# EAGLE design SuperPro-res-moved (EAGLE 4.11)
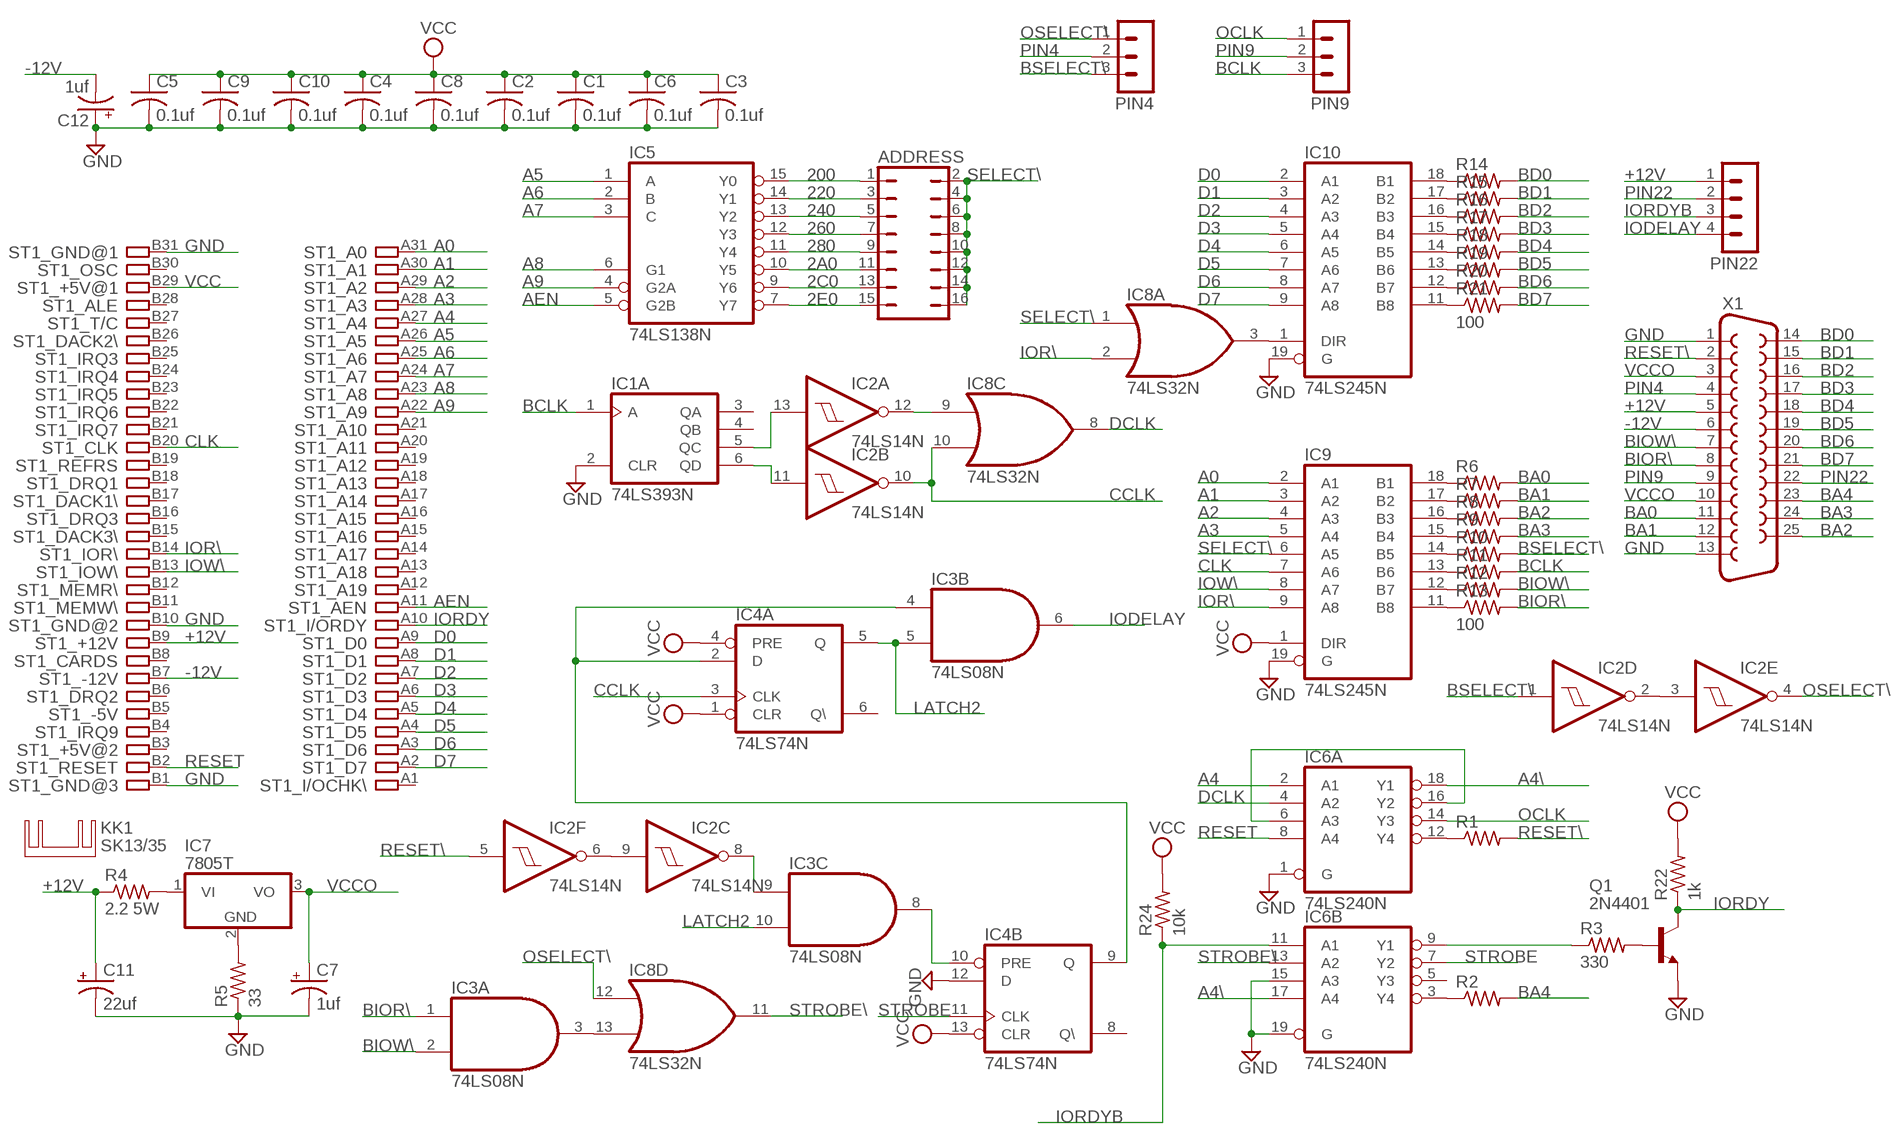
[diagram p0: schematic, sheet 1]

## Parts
ADDRESS  JP8Q  [JP8Q]
C1  0.1uf  C-US050-025X075  [C050-025X075]
C2  0.1uf  C-US050-025X075  [C050-025X075]
C3  0.1uf  C-US050-025X075  [C050-025X075]
C4  0.1uf  C-US050-025X075  [C050-025X075]
C5  0.1uf  C-US050-025X075  [C050-025X075]
C6  0.1uf  C-US050-025X075  [C050-025X075]
C7  1uf  CPOL-USE5-10.5  [E5-10,5]
C8  0.1uf  C-US050-025X075  [C050-025X075]
C9  0.1uf  C-US050-025X075  [C050-025X075]
C10  0.1uf  C-US050-025X075  [C050-025X075]
C11  22uf  CPOL-USE5-10.5  [E5-10,5]
C12  1uf  CPOL-USE5-10.5  [E5-10,5]
IC1  74LS393N  [DIL14]
IC2  74LS14N  [DIL14]
IC3  74LS08N  [DIL14]
IC4  74LS74N  [DIL14]
IC5  74LS138N  [DIL16]
IC6  74LS240N  [DIL20]
IC7  7805T  [TO220H]
IC8  74LS32N  [DIL14]
IC9  74LS245N  [DIL20]
IC10  74LS245N  [DIL20]
KK1  SK13/35  [SK13/35]
PIN4  MA03-1  [MA03-1]
PIN9  MA03-1  [MA03-1]
PIN22  MA04-1  [MA04-1]
Q1  2N4401  2N4416  [TO92]
R1  R-US_0207/10  [0207/10]
R2  R-US_0207/10  [0207/10]
R3  330  R-US_0207/10  [0207/10]
R4  2.2 5W  R-US_0922/22  [0922/22]
R5  33  R-US_0207/10  [0207/10]
R6  R-US_0207/10  [0207/10]
R7  R-US_0207/10  [0207/10]
R8  R-US_0207/10  [0207/10]
R9  R-US_0207/10  [0207/10]
R10  R-US_0207/10  [0207/10]
R11  R-US_0207/10  [0207/10]
R12  R-US_0207/10  [0207/10]
R13  100  R-US_0207/10  [0207/10]
R14  R-US_0207/10  [0207/10]
R15  R-US_0207/10  [0207/10]
R16  R-US_0207/10  [0207/10]
R17  R-US_0207/10  [0207/10]
R18  R-US_0207/10  [0207/10]
R19  R-US_0207/10  [0207/10]
R20  R-US_0207/10  [0207/10]
R21  100  R-US_0207/10  [0207/10]
R22  1k  R-US_0207/10  [0207/10]
R24  10k  R-US_0207/10  [0207/10]
ST1  IBM8BIT  [IBM8BIT]
X1  F25H  [F25H]

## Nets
2A0: ADDRESS.11 IC5.10(Y5)
2C0: ADDRESS.13 IC5.9(Y6)
2E0: ADDRESS.15 IC5.7(Y7)
200: ADDRESS.1 IC5.15(Y0)
220: ADDRESS.3 IC5.14(Y1)
240: ADDRESS.5 IC5.13(Y2)
260: ADDRESS.7 IC5.12(Y3)
280: ADDRESS.9 IC5.11(Y4)
+12V [Power]: C11.+ PIN22.1 R4.1 ST1.B9 X1.5
-12V [Power]: C12.- ST1.B7 X1.6
A0: IC9.2(A1) ST1.A31
A1: IC9.3(A2) ST1.A30
A2: IC9.4(A3) ST1.A29
A3: IC9.5(A4) ST1.A28
A4: IC6.2(A:A1) ST1.A27
A4\: IC6.17(B:A4) IC6.18(A:Y1)
A5: IC5.1(A) ST1.A26
A6: IC5.2(B) ST1.A25
A7: IC5.3(C) ST1.A24
A8: IC5.6(G1) ST1.A23
A9: IC5.4(G2A) ST1.A22
AEN: IC5.5(G2B) ST1.A11
BA0: R6.2 X1.11
BA1: R7.2 X1.12
BA2: R8.2 X1.25
BA3: R9.2 X1.24
BA4: R2.2 X1.23
BCLK: IC1.1(A:A) PIN9.3 R11.2
BD0: R14.2 X1.14
BD1: R15.2 X1.15
BD2: R16.2 X1.16
BD3: R17.2 X1.17
BD4: R18.2 X1.18
BD5: R19.2 X1.19
BD6: R20.2 X1.20
BD7: R21.2 X1.21
BIOR\: IC3.1(A:I0) R13.2 X1.8
BIOW\: IC3.2(A:I1) R12.2 X1.7
BSELECT\: IC2.1(D:I) PIN4.3 R10.2
CCLK: IC2.10(B:O) IC4.3(A:CLK) IC8.10(C:I1)
CLK: IC9.7(A6) ST1.B20
D0: IC10.2(A1) ST1.A9
D1: IC10.3(A2) ST1.A8
D2: IC10.4(A3) ST1.A7
D3: IC10.5(A4) ST1.A6
D4: IC10.6(A5) ST1.A5
D5: IC10.7(A6) ST1.A4
D6: IC10.8(A7) ST1.A3
D7: IC10.9(A8) ST1.A2
DCLK: IC6.4(A:A2) IC8.8(C:O)
GND: C1.2 C2.2 C3.2 C4.2 C5.2 C6.2 C7.- C8.2 C9.2 C10.2 C11.- C12.+ IC1.2(A:CLR) IC4.12(B:D) IC6.1(A:G) IC6.15(B:A3) IC6.19(B:G) IC9.19(G) IC10.19(G) Q1.3(E) R5.1 ST1.B1 ST1.B10 ST1.B31 X1.1 X1.13
IODELAY: IC3.6(B:O) PIN22.4
IOR\: IC8.2(A:I1) IC9.9(A8) ST1.B14
IORDY: Q1.1(C) R22.1 ST1.A10
IORDYB: IC6.11(B:A1) PIN22.3 R24.1
IOW\: IC9.8(A7) ST1.B13
LATCH2: IC3.5(B:I1) IC3.10(C:I1) IC4.5(A:Q)
N$1: IC8.3(A:O) IC10.1(DIR)
N$2 [Power]: IC7.2(GND) R5.2
N$3: IC10.13(B6) R19.1
N$4: IC10.17(B2) R15.1
N$5: IC10.16(B3) R16.1
N$6: IC10.15(B4) R17.1
N$7: IC10.14(B5) R18.1
N$8: IC10.12(B7) R20.1
N$9: IC10.11(B8) R21.1
N$10: IC10.18(B1) R14.1
N$11: IC9.18(B1) R6.1
N$12: IC9.17(B2) R7.1
N$13: IC9.16(B3) R8.1
N$14: IC9.15(B4) R9.1
N$15: IC9.14(B5) R10.1
N$16: IC9.13(B6) R11.1
N$17: IC9.12(B7) R12.1
N$18: IC9.11(B8) R13.1
N$19: IC6.12(A:Y4) R1.1
N$20: IC2.6(F:O) IC2.9(C:I)
N$21: IC2.2(D:O) IC2.3(E:I)
N$22: IC1.6(A:QD) IC2.11(B:I)
N$23: IC6.3(B:Y4) R2.1
N$24: IC1.5(A:QC) IC2.13(A:I)
N$25 [Power]: IC7.1(VI) R4.2
N$26: IC2.12(A:O) IC8.9(C:I0)
N$28: IC6.6(A:A3) IC6.16(A:Y2)
N$29: IC3.3(A:O) IC8.13(D:I1)
N$30: IC3.4(B:I0) IC4.2(A:D) IC4.9(B:Q)
N$32: IC6.9(B:Y1) R3.1
N$33: IC3.8(C:O) IC4.10(B:PRE)
N$34: IC2.8(C:O) IC3.9(C:I0)
N$37: Q1.2(B) R3.2
OCLK: IC6.14(A:Y3) PIN9.1
OSELECT\: IC2.4(E:O) IC8.12(D:I0) PIN4.1
PIN4: PIN4.2 X1.4
PIN9: PIN9.2 X1.9
PIN22 [Power]: PIN22.2 X1.22
RESET: IC6.8(A:A4) ST1.B2
RESET\: IC2.5(F:I) R1.2 X1.2
SELECT\: ADDRESS.2 ADDRESS.4 ADDRESS.6 ADDRESS.8 ADDRESS.10 ADDRESS.12 ADDRESS.14 ADDRESS.16 IC8.1(A:I0) IC9.6(A5)
STROBE: IC4.11(B:CLK) IC6.7(B:Y2)
STROBE\: IC6.13(B:A2) IC8.11(D:O)
VCC [Power]: C1.1 C2.1 C3.1 C4.1 C5.1 C6.1 C8.1 C9.1 C10.1 IC4.1(A:CLR) IC4.4(A:PRE) IC4.13(B:CLR) IC9.1(DIR) R22.2 R24.2 ST1.B29
VCCO [Power]: C7.+ IC7.3(VO) X1.3 X1.10
Unconnected: IC1.3(A:QA) IC1.4(A:QB) IC1.8(B:QD) IC1.9(B:QC) IC1.10(B:QB) IC1.11(B:QA) IC1.12(B:CLR) IC1.13(B:A) IC3.11(D:O) IC3.12(D:I0) IC3.13(D:I1) IC4.6(A:Q\) IC4.8(B:Q\) IC6.5(B:Y3) IC8.4(B:I0) IC8.5(B:I1) IC8.6(B:O) ST1.A1 ST1.A12 ST1.A13 ST1.A14 ST1.A15 ST1.A16 ST1.A17 ST1.A18 ST1.A19 ST1.A20 ST1.A21 ST1.B3 ST1.B4 ST1.B5 ST1.B6 ST1.B8 ST1.B11 ST1.B12 ST1.B15 ST1.B16 ST1.B17 ST1.B18 ST1.B19 ST1.B21 ST1.B22 ST1.B23 ST1.B24 ST1.B25 ST1.B26 ST1.B27 ST1.B28 ST1.B30

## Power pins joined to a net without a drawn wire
GND: IC1.7(P:GND) IC2.7(P:GND) IC3.7(P:GND) IC4.7(P:GND) IC5.8(GND) IC6.10(P:GND) IC8.7(P:GND) IC9.10(GND) IC10.10(GND)
VCC: IC1.14(P:VCC) IC2.14(P:VCC) IC3.14(P:VCC) IC4.14(P:VCC) IC5.16(VCC) IC6.20(P:VCC) IC8.14(P:VCC) IC9.20(VCC) IC10.20(VCC)

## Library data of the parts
ADDRESS = jumper:JP8Q: JUMPER
C1-C6 C8-C10 = rcl:C-US: CAPACITOR, American symbol
C7 C11 C12 = rcl:CPOL-US: POLARIZED CAPACITOR, American symbol
IC1 = 74xx-us:74*393: Dual 4-bit decade and binary COUNTER
IC2 = 74xx-us:74*14: Hex schmitt trigger INVERTER
IC3 = 74xx-us:74*08: Quad 2-input AND gate
IC4 = 74xx-us:74*74: Dual D type positive edge triggered FLIP FLOP, preset and clear
IC5 = 74xx-us:74*138: 3-line to 8-line DECODER/DEMULTIPLEXER
IC6 = 74xx-us:74*240: Octal BUFFER and LINE DRIVER, 3-state
IC7 = linear:78*: Positive VOLTAGE REGULATOR
IC8 = 74xx-us:74*32: Quad 2-input OR gate
IC9 IC10 = 74xx-us:74*245: Octal BUS TRANSCEIVER, 3-state
KK1 = heatsink:SK13/35: HEATSINK
PIN4 PIN9 = con-lstb:MA03-1: PIN HEADER
PIN22 = con-lstb:MA04-1: PIN HEADER
Q1 = transistor-npn:2N4416: NPN Transistor
R1-R22 R24 = rcl:R-US_: RESISTOR, American symbol
ST1 = con-pc:IBM8BIT: 8-bit CARD IBM/PC-AT
X1 = con-subd:F25: SUB-D

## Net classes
1 Power: width 0.762 mm, drill 0.254 mm

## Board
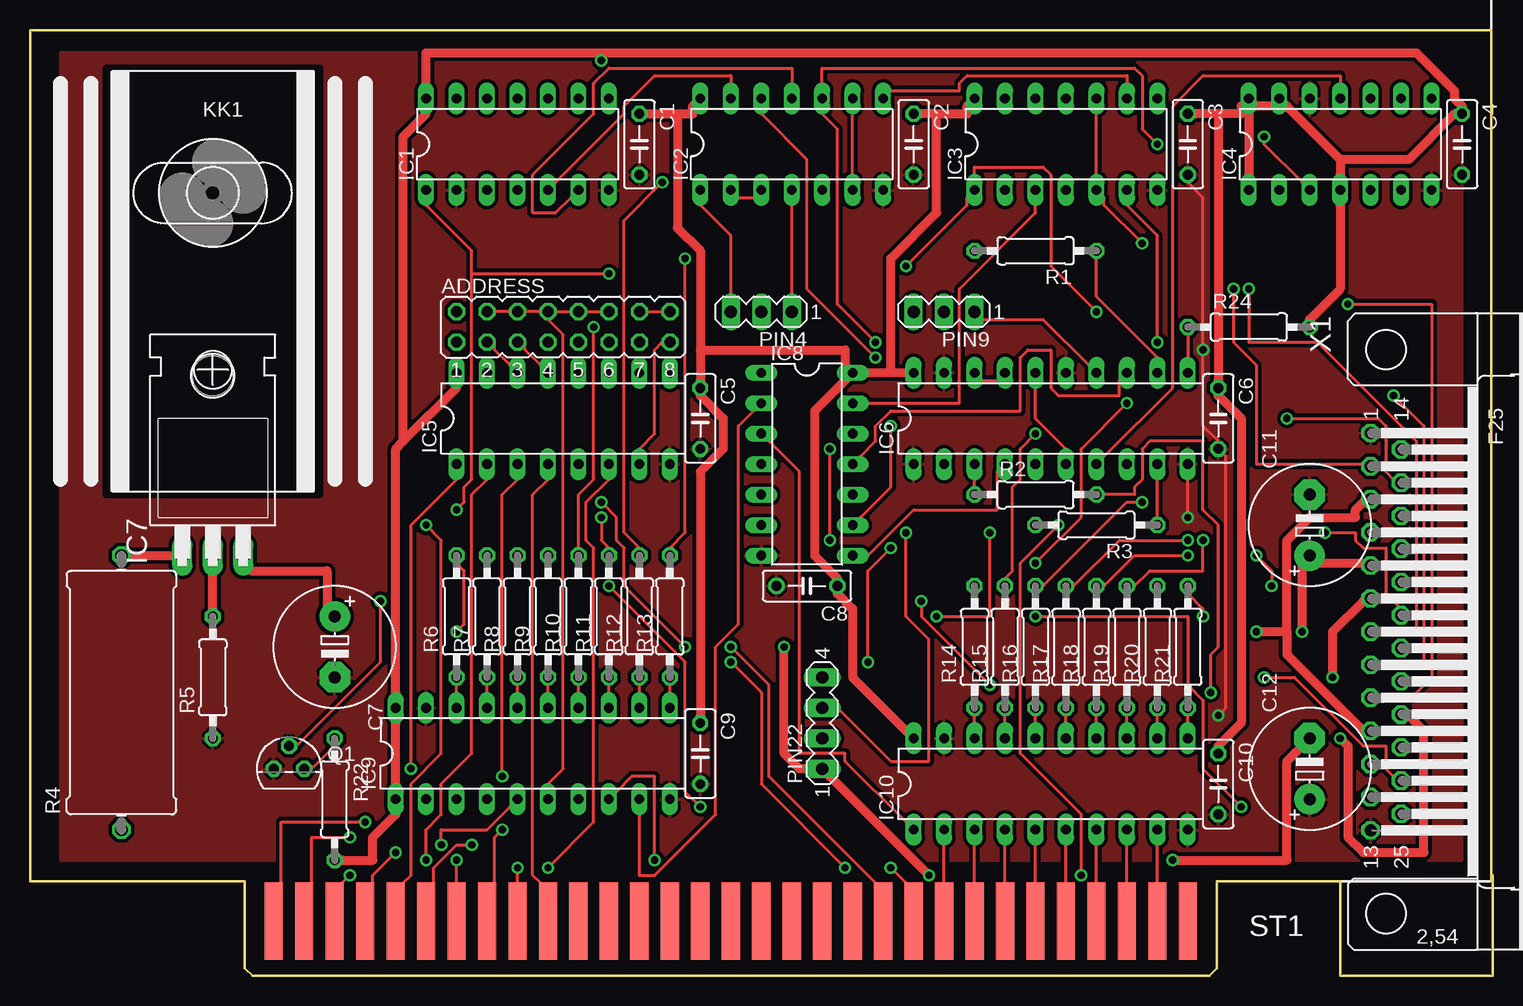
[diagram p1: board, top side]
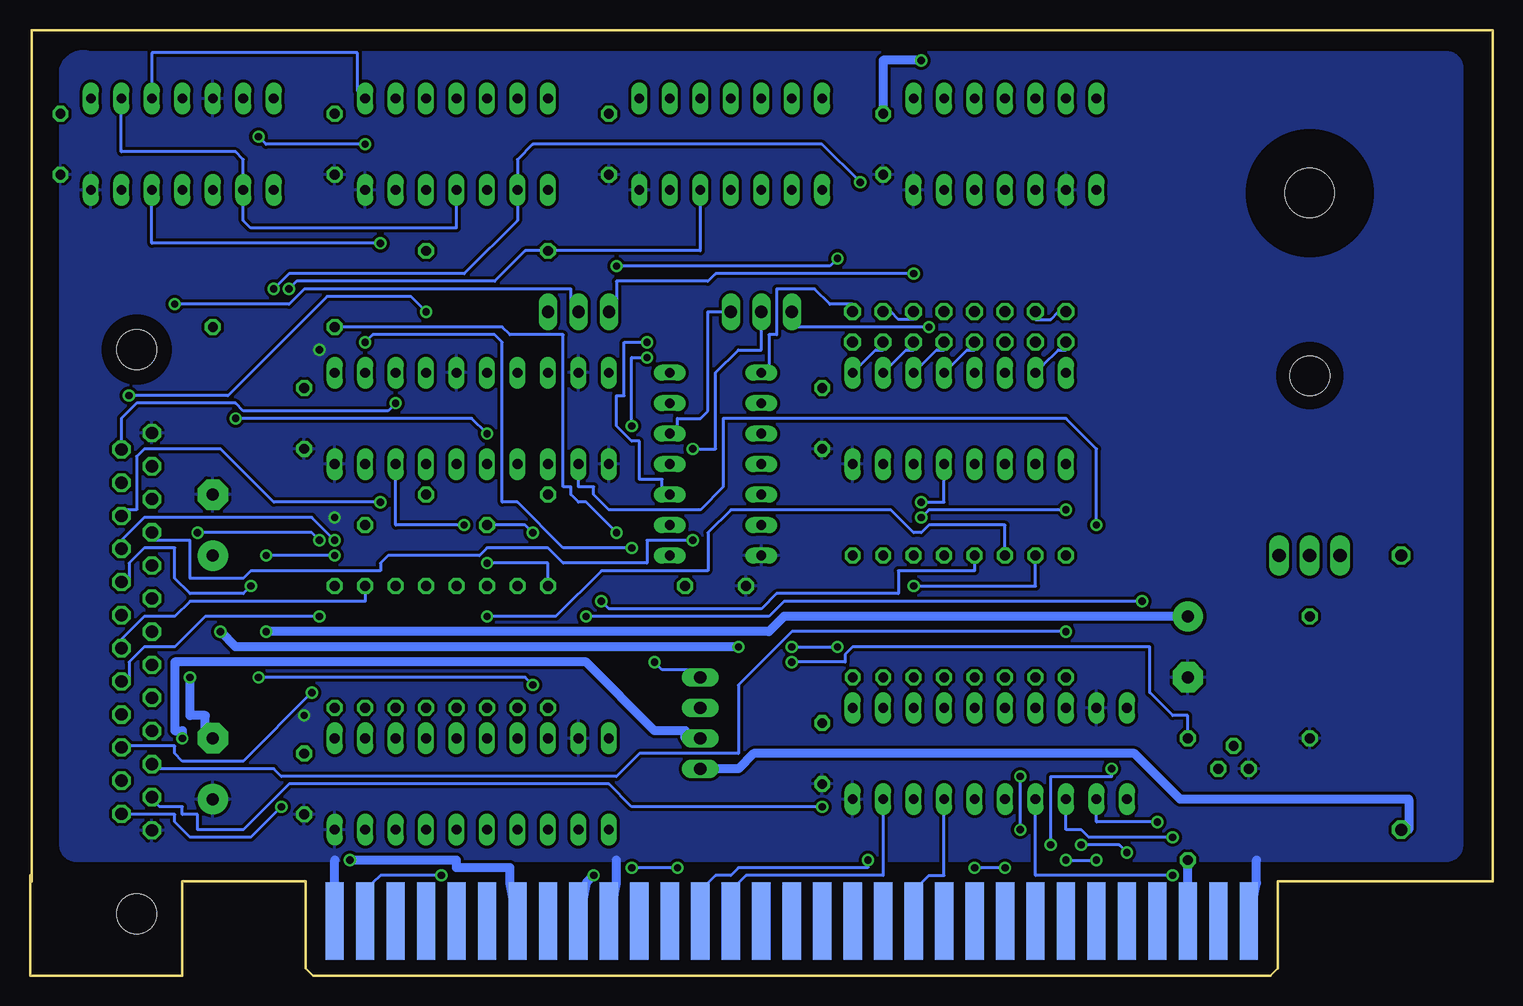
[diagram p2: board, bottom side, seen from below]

Size 121.92 x 78.87 mm. Coordinates in mm from the lower left corner, seen from the top.
Outline: 121.79,7.87 121.79,78.87 0,78.87 0,7.87 17.91,7.87 17.91,0.63 18.54,0 97.79,0 98.3,0 98.93,0.63 98.93,7.87 109.22,7.87 109.22,0 121.92,0 121.92,8.38
Copper layers (1*16): Top 0.035mm / dielectric 1.5mm / Bottom 0.035mm
Design rules "olimex10mil": minimum track width 10mil, minimum drill 24mil, track to track 10mil, track to pad 10mil, pad to pad 10mil, via to via 10mil, smd to smd 10mil, copper to edge 40mil, drill to drill 10mil, minimum pad ring 10mil, minimum via ring 8mil, stop-mask expansion 0mil, vias tented up to drill 0mil, thermal gap 10mil

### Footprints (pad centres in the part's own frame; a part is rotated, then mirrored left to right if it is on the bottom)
JP8Q = drill 0.914 octagon: 1 -8.89,-1.27; 2 -8.89,1.27; 3 -6.35,-1.27; 4 -6.35,1.27; 5 -3.81,-1.27; 6 -3.81,1.27; 7 -1.27,-1.27; 8 -1.27,1.27; 9 1.27,-1.27; 10 1.27,1.27; 11 3.81,-1.27; 12 3.81,1.27; 13 6.35,-1.27; 14 6.35,1.27; 15 8.89,-1.27; 16 8.89,1.27
C050-025X075 = drill 0.813 octagon: 1 -2.54,0; 2 2.54,0
E5-10,5 = drill 1.016 pad 2.54 round: + -2.54,0 | drill 1.016 pad 2.54 octagon: - 2.54,0
DIL14 = drill 0.813 long: 1 -7.62,-3.81; 2 -5.08,-3.81; 3 -2.54,-3.81; 4 0,-3.81; 5 2.54,-3.81; 6 5.08,-3.81; 7 7.62,-3.81; 8 7.62,3.81; 9 5.08,3.81; 10 2.54,3.81; 11 0,3.81; 12 -2.54,3.81; 13 -5.08,3.81; 14 -7.62,3.81
DIL16 = drill 0.813 long: 1 -8.89,-3.81; 2 -6.35,-3.81; 3 -3.81,-3.81; 4 -1.27,-3.81; 5 1.27,-3.81; 6 3.81,-3.81; 7 6.35,-3.81; 8 8.89,-3.81; 9 8.89,3.81; 10 6.35,3.81; 11 3.81,3.81; 12 1.27,3.81; 13 -1.27,3.81; 14 -3.81,3.81; 15 -6.35,3.81; 16 -8.89,3.81
DIL20 = drill 0.813 long: 1 -11.43,-3.81; 2 -8.89,-3.81; 3 -6.35,-3.81; 4 -3.81,-3.81; 5 -1.27,-3.81; 6 1.27,-3.81; 7 3.81,-3.81; 8 6.35,-3.81; 9 8.89,-3.81; 10 11.43,-3.81; 11 11.43,3.81; 12 8.89,3.81; 13 6.35,3.81; 14 3.81,3.81; 15 1.27,3.81; 16 -1.27,3.81; 17 -3.81,3.81; 18 -6.35,3.81; 19 -8.89,3.81; 20 -11.43,3.81
TO220H = drill 1.118 long: 1 -2.54,-10.16; 2 0,-10.16; 3 2.54,-10.16 | hole 3.302: 0,4.826
MA03-1 = drill 1.016 long: 1 -2.54,0; 2 0,0; 3 2.54,0
MA04-1 = drill 1.016 long: 1 -3.81,0; 2 -1.27,0; 3 1.27,0; 4 3.81,0
TO92 = drill 0.813 octagon: 1 1.27,0; 2 0,1.905; 3 -1.27,0
0207/10 = drill 0.813 octagon: 1 -5.08,0; 2 5.08,0
0922/22 = drill 1.016 octagon: 1 -11.43,0; 2 11.43,0
IBM8BIT = smd 1.524 x 6.477: A1 -25.4,5.08; A2 -27.94,5.08; A3 -30.48,5.08; A4 -33.02,5.08; A5 -35.56,5.08; A6 -38.1,5.08; A7 -40.64,5.08; A8 -43.18,5.08; A9 -45.72,5.08; A10 -48.26,5.08; A11 -50.8,5.08; A12 -53.34,5.08; A13 -55.88,5.08; A14 -58.42,5.08; A15 -60.96,5.08; A16 -63.5,5.08; A17 -66.04,5.08; A18 -68.58,5.08; A19 -71.12,5.08; A20 -73.66,5.08; A21 -76.2,5.08; A22 -78.74,5.08; A23 -81.28,5.08; A24 -83.82,5.08; A25 -86.36,5.08; A26 -88.9,5.08; A27 -91.44,5.08; A28 -93.98,5.08; A29 -96.52,5.08; A30 -99.06,5.08; A31 -101.6,5.08 | smd 1.524 x 6.477 bottom: B1 -25.4,5.08; B2 -27.94,5.08; B3 -30.48,5.08; B4 -33.02,5.08; B5 -35.56,5.08; B6 -38.1,5.08; B7 -40.64,5.08; B8 -43.18,5.08; B9 -45.72,5.08; B10 -48.26,5.08; B11 -50.8,5.08; B12 -53.34,5.08; B13 -55.88,5.08; B14 -58.42,5.08; B15 -60.96,5.08; B16 -63.5,5.08; B17 -66.04,5.08; B18 -68.58,5.08; B19 -71.12,5.08; B20 -73.66,5.08; B21 -76.2,5.08; B22 -78.74,5.08; B23 -81.28,5.08; B24 -83.82,5.08; B25 -86.36,5.08; B26 -88.9,5.08; B27 -91.44,5.08; B28 -93.98,5.08; B29 -96.52,5.08; B30 -99.06,5.08; B31 -101.6,5.08
4,1 = hole 4.1: 0,0
F25H = drill 1.016 octagon: 1 -16.561,-1.27; 2 -13.792,-1.27; 3 -11.049,-1.27; 4 -8.28,-1.27; 5 -5.512,-1.27; 6 -2.769,-1.27; 7 0,-1.27; 8 2.769,-1.27; 9 5.512,-1.27; 10 8.28,-1.27; 11 11.049,-1.27; 12 13.792,-1.27; 13 16.561,-1.27; 14 -15.189,1.27; 15 -12.421,1.27; 16 -9.652,1.27; 17 -6.909,1.27; 18 -4.14,1.27; 19 -1.372,1.27; 20 1.372,1.27; 21 4.14,1.27; 22 6.909,1.27; 23 9.652,1.27; 24 12.421,1.27; 25 15.189,1.27 | hole 3.302: -23.52,0; 23.52,0

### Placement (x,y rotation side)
ADDRESS  44.45,54.1 0 top
C1  50.8,69.34 270 top
C2  73.66,69.34 270 top
C3  96.52,69.34 270 top
C4  119.38,69.34 270 top
C5  55.88,46.48 270 top
C6  99.06,46.48 270 top
C7  25.4,27.43 270 top
C8  64.77,32.51 180 top
C9  55.88,18.54 270 top
C10  99.06,16 270 top
C11  106.68,37.59 90 top
C12  106.68,17.27 90 top
IC1  40.64,69.34 0 top
IC2  63.5,69.34 0 top
IC3  86.36,69.34 0 top
IC4  109.22,69.34 0 top
IC5  44.45,46.48 0 top
IC6  85.09,46.48 0 top
IC7  15.24,45.21 0 top
IC8  64.77,42.67 270 top
IC9  41.91,18.54 0 top
IC10  85.09,16 0 top
KK1  15.24,61.72 90 top
PIN4  60.96,55.37 180 top
PIN9  76.2,55.37 180 top
PIN22  66.04,21.08 90 top
Q1  21.59,17.27 0 top
R1  83.82,60.45 180 top
R2  83.82,40.13 0 top
R3  88.9,37.59 180 top
R4  7.62,23.62 90 top
R5  15.24,24.89 90 top
R6  35.56,29.97 90 top
R7  38.1,29.97 90 top
R8  40.64,29.97 90 top
R9  43.18,29.97 90 top
R10  45.72,29.97 90 top
R11  48.26,29.97 90 top
R12  50.8,29.97 90 top
R13  53.34,29.97 90 top
R14  78.74,27.43 90 top
R15  81.28,27.43 90 top
R16  83.82,27.43 90 top
R17  86.36,27.43 90 top
R18  88.9,27.43 90 top
R19  91.44,27.43 90 top
R20  93.98,27.43 90 top
R21  96.52,27.43 90 top
R22  25.4,14.73 270 top
R24  101.6,54.1 0 top
ST1  121.92,-0.51 0 top
U$1  [4,1]  15.24,65.28 0 top
X1  113.03,28.7 270 top

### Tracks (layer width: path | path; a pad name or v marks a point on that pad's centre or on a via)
2A0
  Bottom 0.254: IC5.10 50.16,50.93 48.89,52.2 48.26,52.2 ADDRESS.11
2C0
  Bottom 0.254: IC5.9 52.7,50.93 51.44,52.2 50.8,52.2 ADDRESS.13
2E0
  Top 0.254: IC5.7 50.8,43.94 52.07,45.21 52.07,52.2 52.7,52.83 ADDRESS.15
200
  Bottom 0.254: IC5.15 37.47,50.93 36.2,52.2 35.56,52.2 ADDRESS.1
220
  Top 0.254: IC5.14 40.01,50.93 38.73,52.2 38.73,52.83 ADDRESS.3
240
  Top 0.254: IC5.13 42.55,50.93 41.28,52.2 41.28,52.83 ADDRESS.5
260
  Bottom 0.254: IC5.12 45.09,50.93 43.81,52.2 43.18,52.2 ADDRESS.7
280
  Bottom 0.254: IC5.11 47.62,50.93 46.36,52.2 45.72,52.2 ADDRESS.9
+12V  (via drill 0.61)
  Top 0.762: X1.5 111.12,34.42 107.31,34.42 C11.+ 106.05,34.42 v106.05,28.7 | v62.87,27.43 62.87,18.54 64.13,17.27 64.77,17.27 PIN22.1 66.68,16.64 v74.93,8.38
  Bottom 0.762: R4.1 6.99,12.19 6.99,14.73 26.04,14.73 29.84,18.54 61.59,18.54 62.87,17.27 64.77,17.27 PIN22.1 | v106.05,28.7 104.78,27.43 v62.87,27.43 | v74.93,8.38 75.56,7.75 ST1.B9
-12V  (via drill 0.61)
  Top 0.762: v108.59,24.89 108.59,28.7 111.12,31.24 X1.6 | v95.25,9.65 104.78,9.65 104.78,17.91 106.05,19.18 C12.-
  Bottom 0.762: v108.59,24.89 108.59,21.72 107.31,21.72 107.31,20.45 C12.- | v95.25,9.65 86.36,9.65 86.36,9.02 81.92,9.02 81.92,7.75 ST1.B7
A0  (via drill 0.61)
  Top 0.254: v27.94,12.83 20.96,12.83 20.96,7.75 ST1.A31
  Bottom 0.254: v27.94,12.83 33.02,12.83 33.02,13.46 IC9.2
A1  (via drill 0.61)
  Top 0.254: v26.67,11.56 23.5,11.56 23.5,7.75 ST1.A30
  Bottom 0.254: v26.67,11.56 33.66,11.56 34.29,12.19 35.56,12.19 35.56,13.46 IC9.3
A2  (via drill 0.61)
  Top 0.254: v26.67,8.38 26.04,7.75 ST1.A29
  Bottom 0.254: v26.67,8.38 38.1,8.38 38.1,13.46 IC9.4
A3  (via drill 0.61)
  Top 0.254: v34.29,10.92 34.29,12.19 38.1,12.19 40.01,14.1 IC9.5 | v30.48,10.29 28.58,8.38 28.58,7.75 ST1.A28
  Bottom 0.254: v34.29,10.92 31.12,10.92 v30.48,10.29
A4  (via drill 0.61)
  Top 0.254: v33.02,37.59 34.29,36.32 34.29,18.54 31.75,16 31.75,8.38 31.12,7.75 ST1.A27
  Bottom 0.254: v33.02,37.59 33.02,43.94 35.56,46.48 64.13,46.48 64.13,40.77 66.04,38.86 73.66,38.86 74.93,40.13 74.93,40.77 76.2,40.77 76.2,41.4 IC6.2
A4\
  Top 0.254: IC6.18 79.38,49.66 80.65,49.66 IC6.17
A5  (via drill 0.61)
  Top 0.254: v31.75,17.27 31.75,37.59 35.56,41.4 IC5.1 | v36.83,10.92 35.56,10.92 33.66,9.02 33.66,7.75 ST1.A26
  Bottom 0.254: v31.75,17.27 31.75,16.64 36.83,16.64 v36.83,10.92
A6  (via drill 0.61)
  Top 0.254: v33.02,9.65 33.02,12.19 34.29,13.46 34.29,16 36.83,18.54 36.83,40.13 38.1,41.4 IC5.2 | v35.56,9.65 35.56,7.75 ST1.A25
  Bottom 0.254: v35.56,9.65 v33.02,9.65
A7  (via drill 0.61)
  Top 0.254: v39.37,16.64 39.37,40.13 40.64,41.4 IC5.3 | v39.37,12.19 38.73,11.56 38.73,7.75 ST1.A24
  Bottom 0.254: v39.37,12.19 v39.37,16.64
A8  (via drill 0.61)
  Top 0.254: v43.18,9.02 46.99,12.83 46.99,35.69 46.36,36.32 46.36,39.5 48.26,41.4 IC5.6 | v40.64,9.02 40.64,7.75 ST1.A23
  Bottom 0.254: v40.64,9.02 v43.18,9.02
A9
  Top 0.254: IC5.4 43.18,41.4 41.91,40.13 41.91,8.38 42.55,7.75 ST1.A22
AEN  (via drill 0.61)
  Top 0.254: v47.62,39.5 48.89,38.23 48.89,36.32 49.53,35.69 49.53,32.51 v54.61,27.43 | v58.42,27.43 61.59,24.26 61.59,16.64 70.48,7.75 ST1.A11
  Bottom 0.254: v47.62,39.5 45.72,39.5 45.72,41.4 IC5.5 | v58.42,27.43 v54.61,27.43
BA0  (via drill 0.61)
  Top 0.254: v35.56,28.7 36.2,29.34 36.2,33.78 35.56,34.42 R6.2
  Bottom 0.254: v35.56,28.7 58.42,28.7 62.87,24.26 62.87,18.54 71.12,18.54 73.03,16.64 100.97,16.64 101.6,17.27 111.12,17.27 X1.11
BA1  (via drill 0.61)
  Top 0.254: v48.26,32.51 54.61,26.16 54.61,15.37 v55.88,14.1
  Bottom 0.254: v48.26,32.51 38.1,32.51 38.1,34.42 R7.2 | v55.88,14.1 71.75,14.1 73.66,16 100.33,16 104.14,12.19 107.95,12.19 107.95,13.46 109.22,13.46 109.22,14.1 111.12,14.1 111.76,14.73 X1.12
BA2  (via drill 0.61)
  Top 0.254: v83.82,29.97 96.52,29.97 96.52,24.26 97.79,22.99 97.79,17.27 v100.97,14.1
  Bottom 0.254: v83.82,29.97 78.11,29.97 74.3,33.78 65.41,33.78 65.41,36.96 63.5,38.86 50.16,38.86 48.26,36.96 47.62,36.96 46.99,37.59 40.64,37.59 40.64,35.69 R8.2 | v100.97,14.1 103.5,11.56 108.59,11.56 109.86,12.83 109.86,13.46 113.67,13.46 X1.25
BA3  (via drill 0.61)
  Top 0.254: v74.3,31.24 74.3,29.97 v80.01,24.26 | v102.87,24.89 105.41,24.89 111.12,19.18 113.03,19.18 113.03,17.27 113.67,16.64 X1.24
  Bottom 0.254: v74.3,31.24 73.66,30.61 60.96,30.61 59.69,31.88 49.53,31.88 49.53,33.78 43.18,33.78 43.18,34.42 R9.2 | v80.01,24.26 80.65,24.89 v102.87,24.89
BA4  (via drill 0.61)
  Top 0.254: v98.42,23.62 98.42,26.8 99.06,27.43 99.06,37.59 97.79,38.86 97.79,44.58 93.34,44.58 92.71,43.94 92.71,41.4 92.08,40.77 92.08,40.13 89.53,40.13 R2.2
  Bottom 0.254: v98.42,23.62 104.14,17.91 109.22,17.91 109.86,18.54 109.86,19.18 113.67,19.18 X1.23
BCLK  (via drill 0.61)
  Top 0.254: v47.62,38.23 47.62,36.32 48.26,35.69 R11.2 | v35.56,38.86 36.2,39.5 36.2,40.77 36.83,41.4 36.83,58.55 | 36.83,58.55 36.83,60.45 33.02,64.26 IC1.1 | 36.83,58.55 v48.26,58.55
  Bottom 0.254: v47.62,38.23 46.99,38.86 v35.56,38.86 | v48.26,58.55 64.77,58.55 65.41,57.91 73.03,57.91 73.03,56.01 PIN9.3
BD0  (via drill 0.61)
  Top 0.254: v83.82,34.42 87.63,38.23 87.63,43.94 v91.44,47.75
  Bottom 0.254: v83.82,34.42 78.74,34.42 78.74,33.15 R14.2 | v91.44,47.75 92.08,47.12 104.14,47.12 104.78,47.75 113.03,47.75 114.3,46.48 114.3,44.58 X1.14
BD1  (via drill 0.61)
  Top 0.254: v83.82,45.21 82.55,43.94 82.55,41.4 81.92,40.77 81.92,33.78 81.28,33.15 R15.2 | v104.78,46.48 112.39,46.48 113.03,45.85 113.03,42.04 113.67,41.4 X1.15
  Bottom 0.254: v83.82,45.21 85.09,46.48 v104.78,46.48
BD2  (via drill 0.61)
  Top 0.254: v92.71,39.5 91.44,39.5 84.45,32.51 R16.2
  Bottom 0.254: v92.71,39.5 101.6,39.5 106.05,43.94 112.39,43.94 113.03,43.31 113.03,38.86 114.3,38.86 X1.16
BD3  (via drill 0.61)
  Top 0.254: v96.52,36.32 90.81,36.32 87,32.51 R17.2
  Bottom 0.254: v96.52,36.32 98.42,38.23 112.39,38.23 114.3,36.32 X1.17
BD4  (via drill 0.61)
  Top 0.254: v96.52,35.05 92.08,35.05 89.53,32.51 R18.2 | v102.23,35.05 103.5,33.78 v103.5,32.51
  Bottom 0.254: v96.52,35.05 v102.23,35.05 | v103.5,32.51 104.14,31.88 108.59,31.88 109.86,33.15 109.86,35.69 112.39,35.69 113.67,34.42 113.67,33.15 X1.18
BD5  (via drill 0.61)
  Top 0.254: v97.79,36.32 97.79,33.78 93.34,33.78 92.08,32.51 R19.2 | v107.95,36.96 110.49,36.96 110.49,36.32 111.12,35.69 113.03,35.69 113.03,31.88 114.3,30.61 X1.19
  Bottom 0.254: v97.79,36.32 98.42,36.96 v107.95,36.96
BD6
  Bottom 0.254: R20.2 93.98,31.88 93.98,31.24 108.59,31.24 109.86,29.97 112.39,29.97 114.3,28.07 X1.20
BD7  (via drill 0.61)
  Top 0.254: v97.79,29.97 97.79,30.61 96.52,31.88 R21.2
  Bottom 0.254: v97.79,29.97 107.31,29.97 109.86,27.43 112.39,27.43 113.67,26.16 113.67,24.89 X1.21
BIOR\  (via drill 0.61)
  Top 0.254: v54.61,59.82 54.61,36.96 53.34,35.69 R13.2 | v73.03,59.18 78.11,64.26 78.11,64.9 IC3.1 78.74,66.8 78.74,67.44 84.45,67.44 85.09,66.8 85.09,59.18 v88.9,55.37 | v113.67,48.39 116.2,45.85 116.2,26.16 112.39,26.16 X1.8
  Bottom 0.254: v54.61,59.82 55.25,59.18 v73.03,59.18 | v113.67,48.39 105.41,48.39 97.16,56.64 90.17,56.64 v88.9,55.37
BIOW\  (via drill 0.61)
  Top 0.254: v52.7,66.17 49.53,62.99 49.53,36.96 50.8,35.69 R12.2 | v101.6,57.28 101.6,52.83 107.31,52.83 115.57,44.58 115.57,28.7 112.39,28.7 X1.7
  Bottom 0.254: v52.7,66.17 55.88,69.34 80.01,69.34 81.28,68.07 81.28,66.8 IC3.2 81.28,64.26 81.28,62.99 85.72,58.55 100.33,58.55 v101.6,57.28
BSELECT\  (via drill 0.61)
  Top 0.254: v46.99,54.1 46.99,41.4 45.72,40.13 45.72,35.69 R10.2 | IC2.1 55.88,64.26 58.42,61.72 58.42,56.64 PIN4.3
  Bottom 0.254: v46.99,54.1 58.42,54.1 PIN4.3
CCLK  (via drill 0.61)
  Top 0.254: v70.48,52.83 67.31,56.01 67.31,70.61 66.04,71.88 IC2.10 66.04,74.42 66.04,75.69 92.08,75.69 92.71,75.06 92.71,70.61 v93.98,69.34 | v102.87,69.98 102.87,69.34 106.05,66.17 IC4.3
  Bottom 0.254: v70.48,52.83 72.39,52.83 72.39,48.39 73.03,48.39 73.03,45.85 71.75,44.58 71.12,44.58 71.12,41.4 69.22,41.4 69.22,40.77 IC8.10 | v102.87,69.98 102.23,69.34 v93.98,69.34
CLK
  Bottom 0.254: IC9.7 45.72,13.46 45.72,8.38 46.99,8.38 47.62,7.75 ST1.B20
D0
  Top 0.254: IC10.2 76.2,10.92 76.2,7.75 ST1.A9
D1
  Top 0.254: IC10.3 78.74,10.92 78.74,7.75 ST1.A8
D2
  Top 0.254: IC10.4 81.28,10.92 81.28,7.75 ST1.A7
D3
  Top 0.254: IC10.5 83.82,10.92 83.82,7.75 ST1.A6
D4
  Top 0.254: IC10.6 86.36,10.92 86.36,7.75 ST1.A5
D5
  Top 0.254: IC10.7 88.9,10.92 88.9,7.75 ST1.A4
D6
  Top 0.254: IC10.8 91.44,10.92 91.44,7.75 ST1.A3
D7
  Top 0.254: IC10.9 93.98,10.92 93.98,7.75 ST1.A2
DCLK
  Top 0.254: IC8.8 69.85,35.05 73.66,38.86 80.65,38.86 80.65,42.04 IC6.4
GND  (via drill 0.61)
  Top 0.254: C3.2 96.52,66.17 97.79,64.9 v97.79,52.2 97.79,45.85 99.06,44.58 C6.2 99.7,43.31 99.7,22.35 v99.06,21.72 | v96.52,38.23 96.52,41.4 IC6.10
  Bottom 0.762: 19.69,9.65 19.69,7.75 ST1.B31 | 73.03,9.65 73.03,7.75 ST1.B10 | 96.52,9.65 96.52,7.75 ST1.B1
  pour Bottom (isolate 0.254): 2.54,10.92 2.54,75.69 arc-90 3.81,76.96 116.84,76.96 arc-90 119.38,75.69 119.38,10.92 arc-90 118.11,9.65 3.81,9.65 arc-90
  pour Top (isolate 0.305): 2.54,76.96 2.54,9.65 119.38,9.65 119.38,76.96
IODELAY  (via drill 0.61)
  Top 0.254: v93.98,52.83 93.98,61.72 91.44,64.26 IC3.6 | v71.75,35.69 69.85,33.78 v69.85,26.16
  Bottom 0.254: v93.98,52.83 93.34,53.47 83.19,53.47 82.55,52.83 82.55,39.5 81.28,39.5 77.47,35.69 v71.75,35.69 | v69.85,26.16 69.22,25.53 66.68,25.53 PIN22.4
IOR\
  Top 0.254: IC8.2 60.33,47.12 59.05,45.85 59.05,29.34 57.15,27.43 57.15,13.46 52.07,8.38 50.8,8.38 50.8,13.46 IC9.9
  Bottom 0.254: IC9.9 50.8,13.46 50.8,8.38 62.23,8.38 62.87,7.75 ST1.B14
IORDY  (via drill 0.61)
  Top 0.254: Q1.1 23.5,17.27 25.4,19.18 R22.1 | v58.42,26.16 60.96,23.62 60.96,16 v67.94,9.02 | v71.75,9.02 73.03,7.75 ST1.A10
  Bottom 0.254: v58.42,26.16 53.98,26.16 53.98,26.8 53.34,27.43 28.58,27.43 28.58,23.62 26.67,21.72 25.4,21.72 25.4,20.45 R22.1 | v67.94,9.02 v71.75,9.02
IORDYB  (via drill 0.61)
  Top 0.254: IC6.11 96.52,51.56 96.52,53.47 R24.1 | v73.03,36.96 73.03,29.97 74.93,28.07 74.93,17.91 71.75,17.91 67.31,22.35 PIN22.3
  Bottom 0.254: v73.03,36.96 75.56,39.5 76.2,39.5 76.84,40.13 76.84,40.77 77.47,40.77 77.47,53.47 81.92,53.47 82.55,54.1 95.89,54.1 R24.1
IOW\  (via drill 0.61)
  Top 0.254: v52.07,9.65 52.07,16.64 50.16,16.64 48.89,15.37 IC9.8
  Bottom 0.254: v52.07,9.65 52.07,9.02 62.87,9.02 63.5,8.38 64.77,8.38 65.41,7.75 ST1.B13
LATCH2  (via drill 0.61)
  Top 0.254: IC3.10 88.9,71.88 88.9,66.8 IC3.5 89.53,64.9 89.53,64.26 v92.71,61.09
  Bottom 0.254: v92.71,61.09 111.76,61.09 111.76,64.26 IC4.5
N$1
  Top 0.254: IC10.1 73.03,12.83 67.94,17.91 67.94,18.54 64.13,18.54 64.13,42.04 61.59,44.58 IC8.3
N$2
  Top 0.762: R5.2 15.24,30.61 15.24,33.78 IC7.2
N$3
  Top 0.254: IC10.13 91.44,21.08 91.44,21.72 R19.1
N$4
  Top 0.254: IC10.17 81.28,21.08 81.28,21.72 R15.1
N$5
  Top 0.254: IC10.16 83.82,21.08 83.82,21.72 R16.1
N$6
  Top 0.254: IC10.15 86.36,21.08 86.36,21.72 R17.1
N$7
  Top 0.254: IC10.14 88.9,21.08 88.9,21.72 R18.1
N$8
  Top 0.254: IC10.12 93.98,21.08 93.98,21.72 R20.1
N$9
  Top 0.254: IC10.11 96.52,21.08 96.52,21.72 R21.1
N$10
  Top 0.254: IC10.18 78.74,21.08 78.74,21.72 R14.1
N$11
  Top 0.254: IC9.18 35.56,23.62 35.56,24.26 R6.1
N$12
  Top 0.254: IC9.17 38.1,23.62 38.1,24.26 R7.1
N$13
  Top 0.254: IC9.16 40.64,23.62 40.64,24.26 R8.1
N$14
  Top 0.254: IC9.15 43.18,23.62 43.18,24.26 R9.1
N$15
  Top 0.254: IC9.14 45.72,23.62 45.72,24.26 R10.1
N$16
  Top 0.254: IC9.13 48.26,23.62 48.26,24.26 R11.1
N$17
  Top 0.254: IC9.12 50.8,23.62 50.8,24.26 R12.1
N$18
  Top 0.254: IC9.11 53.34,23.62 53.34,24.26 R13.1
N$19
  Top 0.254: IC6.12 93.98,51.56 88.9,56.64 88.9,59.82 R1.1
N$20
  Top 0.254: IC2.6 68.58,66.8 68.58,71.88 IC2.9
N$21
  Top 0.254: IC2.2 59.05,64.9 60.33,64.9 IC2.3
N$22
  Top 0.254: IC1.6 45.09,64.9 43.81,63.63 41.91,63.63 41.91,66.8 46.99,71.88 46.99,74.42 48.26,75.69 63.5,75.69 63.5,74.42 IC2.11
N$23
  Top 0.254: R2.1 78.74,40.77 78.74,41.4 IC6.3
N$24
  Top 0.254: IC1.5 43.81,66.17 49.53,71.88 49.53,72.52 52.07,75.06 58.42,75.06 58.42,74.42 IC2.13
N$25
  Top 0.762: R4.2 8.26,35.05 12.07,35.05 IC7.1
N$26  (via drill 0.61)
  Top 0.254: v71.75,45.85 71.75,40.77 69.22,38.23 IC8.9 | v70.48,51.56 64.77,57.28 64.77,68.07 60.96,71.88 IC2.12
  Bottom 0.254: v71.75,45.85 71.75,51.56 v70.48,51.56
N$28
  Top 0.254: IC6.6 86.36,43.94 83.82,46.48 83.82,49.02 IC6.16
N$29
  Top 0.254: IC8.13 69.85,47.75 77.47,47.75 77.47,57.28 83.82,63.63 83.82,64.26 IC3.3
N$30
  Bottom 0.254: IC3.4 86.36,64.26 86.36,62.36 103.5,62.36 104.14,62.99 104.14,64.26 IC4.2 104.14,66.8 104.14,68.07 104.78,68.71 114.3,68.71 114.3,71.88 IC4.9
N$32
  Top 0.254: R3.1 93.98,38.23 93.98,41.4 IC6.9
N$33
  Bottom 0.254: IC3.8 94.61,73.79 94.61,76.96 111.76,76.96 111.76,74.42 IC4.10
N$34
  Top 0.254: IC2.8 71.75,73.79 77.47,73.79 77.47,74.42 78.11,75.06 91.44,75.06 91.44,74.42 IC3.9
N$37  (via drill 0.61)
  Top 0.254: v29.21,31.24 29.21,26.16 22.23,19.18 Q1.2 | v75.56,29.97 80.01,29.97 v80.01,36.96
  Bottom 0.254: v29.21,31.24 59.05,31.24 60.33,29.97 v75.56,29.97 | v80.01,36.96 80.65,37.59 83.19,37.59 R3.2
OCLK
  Top 0.254: IC6.14 88.27,50.93 84.45,54.74 79.38,54.74 PIN9.1
OSELECT\
  Top 0.254: IC2.4 63.5,64.26 63.5,56.64 PIN4.1
  Bottom 0.254: IC8.12 67.94,45.85 67.94,46.48 66.04,46.48 65.41,47.12 65.41,55.37 64.13,55.37 PIN4.1
PIN4  (via drill 0.61)
  Top 0.254: v66.68,36.32 v66.68,43.94
  Bottom 0.254: v66.68,43.94 64.77,43.94 64.77,50.29 62.87,52.2 60.96,52.2 60.96,54.1 PIN4.2 | v66.68,36.32 70.48,36.32 70.48,34.42 77.47,34.42 78.74,35.69 83.82,35.69 84.45,35.05 92.08,35.05 92.71,34.42 92.71,33.78 103.5,33.78 104.14,33.15 108.59,33.15 108.59,36.32 111.76,36.32 X1.4
PIN9  (via drill 0.61)
  Top 0.254: v109.86,56.01 116.84,56.01 116.84,24.89 114.94,22.99 112.39,22.99 X1.9
  Bottom 0.254: v109.86,56.01 100.33,56.01 99.06,57.28 76.84,57.28 76.84,56.01 PIN9.2
PIN22  (via drill 0.61)
  Top 0.762: v109.22,19.81 109.86,19.18 109.86,11.56 111.12,10.29 116.2,10.29 116.2,20.45 114.94,21.72 X1.22
  Bottom 0.762: v109.22,19.81 109.22,20.45 109.86,20.45 109.86,26.16 75.56,26.16 69.85,20.45 67.31,20.45 67.31,19.81 PIN22.2
RESET  (via drill 0.61)
  Top 0.254: v85.72,37.59 82.55,34.42 82.55,18.54 87.63,13.46 v87.63,8.38
  Bottom 0.254: v85.72,37.59 91.44,37.59 91.44,41.4 IC6.8 | v87.63,8.38 92.71,8.38 93.34,7.75 ST1.B2
RESET\  (via drill 0.61)
  Top 0.254: v100.33,57.28 100.33,52.83 102.23,50.93 102.23,42.67 111.12,42.67 X1.2
  Bottom 0.254: IC2.5 66.04,64.26 66.04,60.45 78.11,60.45 R1.2 79.38,60.45 80.65,60.45 83.19,57.91 99.7,57.91 v100.33,57.28
SELECT\
  Top 0.254: ADDRESS.14 51.44,55.37 52.7,55.37 ADDRESS.16 | ADDRESS.4 38.73,55.37 40.01,55.37 ADDRESS.6 41.28,55.37 42.55,55.37 ADDRESS.8 | IC9.6 43.18,16 44.45,17.27 44.45,53.47 43.18,54.74 ADDRESS.8 | ADDRESS.8 43.81,55.37 45.09,55.37 ADDRESS.10 46.36,55.37 47.62,55.37 ADDRESS.12
  Bottom 0.254: IC8.1 60.33,50.93 60.33,53.47 59.69,53.47 59.69,57.28 56.52,57.28 55.25,56.01 53.34,56.01 ADDRESS.16 | ADDRESS.2 36.2,55.37 36.83,54.74 38.1,54.74 ADDRESS.4 | ADDRESS.14 50.16,55.37 49.53,54.74 48.26,54.74 ADDRESS.12
STROBE
  Top 0.254: IC6.7 89.53,43.31 95.25,49.02 95.25,72.52 97.79,75.06 109.22,75.06 109.22,74.42 IC4.11
STROBE\
  Top 0.254: IC8.11 69.22,43.31 70.48,44.58 70.48,45.85 71.75,47.12 82.55,47.12 82.55,51.56 83.19,52.2 85.09,52.2 85.09,49.02 85.72,48.39 90.81,48.39 90.81,49.66 IC6.13
VCC  (via drill 0.61)
  Top 0.762: 53.98,71.88 55.25,71.88 55.25,72.52 IC2.14 | 53.98,71.88 51.44,71.88 C1.1 | C9.1 55.88,21.72 55.88,42.04 57.79,43.94 57.79,46.48 55.88,48.39 C5.1 55.88,49.66 55.88,52.2 | 53.98,71.88 53.98,62.36 55.88,60.45 55.88,52.2 | 75.56,71.88 78.11,71.88 78.11,72.52 IC3.14 | 75.56,71.88 74.3,71.88 C2.1 | 71.75,50.29 73.03,50.29 IC6.20 | 71.75,50.29 69.85,50.29 IC8.14 | IC10.20 73.03,20.45 68.58,24.89 68.58,30.61 67.31,31.88 C8.1 67.31,33.15 65.41,35.05 65.41,47.12 67.94,49.66 IC8.14 | 75.56,71.88 75.56,63.63 71.75,59.82 71.75,50.29 | 55.88,52.2 67.94,52.2 67.94,50.93 IC8.14 | C10.1 99.06,19.18 100.97,21.08 100.97,46.48 99.06,48.39 C6.1 99.06,49.66 99.06,71.88 | IC4.1 101.6,66.8 101.6,71.88 IC4.14 | 99.06,71.88 100.97,71.88 100.97,72.52 IC4.14 | 99.06,71.88 97.16,71.88 C3.1 | IC4.14 102.23,72.52 103.5,72.52 IC4.13 104.78,72.52 109.22,68.07 | R24.2 106.68,54.74 109.22,57.28 109.22,64.26 IC4.4 109.22,66.8 109.22,68.07 | 109.22,68.07 114.94,68.07 118.75,71.88 C4.1 119.38,72.52 118.75,73.15 118.75,73.79 115.57,76.96 47.62,76.96 | 31.12,44.58 30.48,43.94 30.48,23.62 IC9.20 30.48,21.08 30.48,16 IC9.1 30.48,13.46 28.58,11.56 28.58,9.65 26.04,9.65 R22.2 | 31.12,44.58 35.56,49.02 IC5.16 | 31.12,44.58 31.12,69.98 33.02,71.88 IC1.14 33.02,74.42 33.02,76.96 47.62,76.96 | 47.62,76.96 v47.62,76.33
  Bottom 0.762: R22.2 25.4,9.02 25.4,7.75 ST1.B29 | v47.62,76.33 50.8,76.33 50.8,72.52 C1.1
VCCO  (via drill 0.61)
  Top 0.762: IC7.3 18.42,33.78 24.77,33.78 24.77,30.61 C7.+ | 104.78,28.7 104.78,36.32 106.68,38.23 110.49,38.23 110.49,38.86 111.12,39.5 X1.3 | 104.78,28.7 104.78,26.8 111.12,20.45 X1.10 | v102.23,28.7 104.78,28.7
  Bottom 0.762: v102.23,28.7 60.33,28.7 59.05,29.97 26.04,29.97 C7.+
